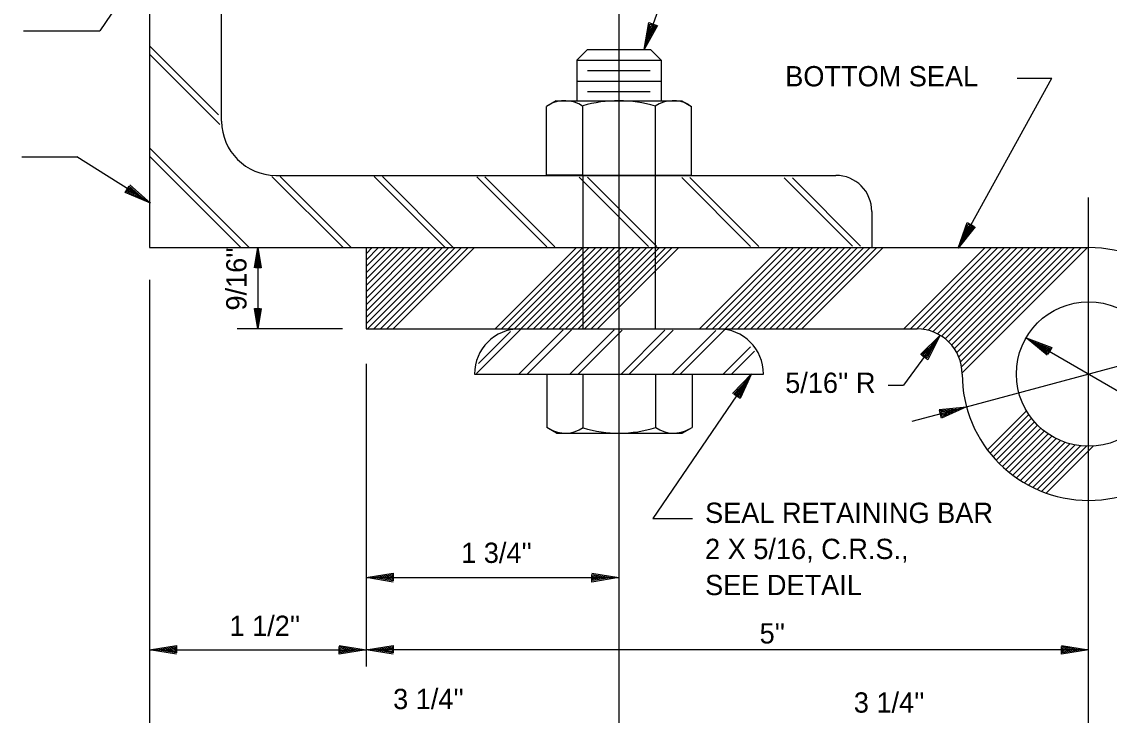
# Model space of a CAD drawing. Extents: x 22371.58 to 22374.41, y 22370.57 to 22372.4.
# Drawn here: x 22373.34 to 22373.968, y 22371.536 to 22371.936 of the extents above; entities that cross this region are included whole.
import ezdxf

# ---------------------------------------------------------------- set-up
doc = ezdxf.new("R2010")
doc.units = 0
for name, color, linetype in [('S-ANNO-DIMS', 7, 'Continuous'), ('S-ANNO-TEXT', 7, 'Continuous'), ('S-GATE-SEAL', 7, 'Continuous'), ('S-SECT-MISC', 7, 'Continuous')]:
    doc.layers.add(name, color=color, linetype=linetype)

msp = doc.modelspace()

# ---------------------------------------------------------------- linework, layer by layer
at = {"layer": 'S-ANNO-DIMS'}
for p, q in [((22373.43491, 22372.00398), (22373.38549, 22371.93085)), ((22373.6993, 22371.92005), (22373.71761, 22371.97098)), ((22373.68487, 22371.95267), (22373.68487, 22371.52103)), ((22373.34148, 22371.93085), (22373.38549, 22371.93085)), ((22373.70077, 22371.92412), (22373.70077, 22371.92412)), ((22373.6993, 22371.92005), (22373.6993, 22371.92005)), ((22373.8805, 22371.8054), (22373.9346, 22371.90356)), ((22373.91461, 22371.90356), (22373.9346, 22371.90356)), ((22373.34041, 22371.85808), (22373.37223, 22371.85808)), ((22373.41459, 22371.83149), (22373.37223, 22371.85808)), ((22373.41092, 22371.83379), (22373.41092, 22371.83379)), ((22373.41459, 22371.83149), (22373.41459, 22371.83149)), ((22373.95571, 22371.51808), (22373.95571, 22371.83464)), ((22373.47654, 22371.80582), (22373.47654, 22371.75894)), ((22373.47654, 22371.80582), (22373.47654, 22371.80582)), ((22373.8805, 22371.8054), (22373.8805, 22371.8054)), ((22373.88259, 22371.80919), (22373.88259, 22371.80919)), ((22373.47654, 22371.80257), (22373.47654, 22371.80257)), ((22373.41404, 22371.78718), (22373.41404, 22371.51808)), ((22373.47654, 22371.76219), (22373.47654, 22371.76219)), ((22373.52536, 22371.75894), (22373.46471, 22371.75894)), ((22373.47654, 22371.75894), (22373.47654, 22371.75894)), ((22373.87009, 22371.75527), (22373.84894, 22371.7264)), ((22373.87009, 22371.75527), (22373.87009, 22371.75527)), ((22373.91964, 22371.75373), (22373.99181, 22371.71206)), ((22373.91964, 22371.75373), (22373.91964, 22371.75373)), ((22373.86753, 22371.75177), (22373.86753, 22371.75177)), ((22373.88529, 22371.71402), (22374.02616, 22371.75177)), ((22373.92339, 22371.75156), (22373.92339, 22371.75156)), ((22373.53904, 22371.73875), (22373.53904, 22371.56422)), ((22373.76132, 22371.73303), (22373.70447, 22371.6496)), ((22373.75888, 22371.72944), (22373.75888, 22371.72944)), ((22373.76132, 22371.73303), (22373.76132, 22371.73303)), ((22373.84018, 22371.7264), (22373.84894, 22371.7264)), ((22373.85399, 22371.70563), (22373.8853, 22371.71402)), ((22373.88111, 22371.71289), (22373.88111, 22371.71289)), ((22373.8853, 22371.71402), (22373.8853, 22371.71402)), ((22373.70447, 22371.6496), (22373.72723, 22371.6496)), ((22373.53904, 22371.61548), (22373.68487, 22371.61548)), ((22373.53904, 22371.61548), (22373.53904, 22371.61548)), ((22373.54337, 22371.61548), (22373.54337, 22371.61548)), ((22373.68054, 22371.61548), (22373.68054, 22371.61548)), ((22373.68487, 22371.61548), (22373.68487, 22371.61548)), ((22373.41404, 22371.57381), (22373.53904, 22371.57381)), ((22373.41404, 22371.57381), (22373.41404, 22371.57381)), ((22373.41837, 22371.57381), (22373.41837, 22371.57381)), ((22373.53471, 22371.57381), (22373.53471, 22371.57381)), ((22373.95571, 22371.57381), (22373.53904, 22371.57381)), ((22373.53904, 22371.57381), (22373.53904, 22371.57381)), ((22373.54337, 22371.57381), (22373.54337, 22371.57381)), ((22373.95137, 22371.57381), (22373.95137, 22371.57381)), ((22373.95571, 22371.57381), (22373.95571, 22371.57381))]:
    msp.add_line(p, q, dxfattribs=at)
for points in [[(22373.70701, 22371.93384), (22373.6993, 22371.92005), (22373.70214, 22371.93559), (22373.7063, 22371.93409), (22373.70077, 22371.92412), (22373.70269, 22371.93467), (22373.70536, 22371.93372), (22373.70217, 22371.92805), (22373.70326, 22371.93377), (22373.70435, 22371.93337), (22373.70364, 22371.93212)], [(22373.40277, 22371.84196), (22373.41459, 22371.83149), (22373.40002, 22371.83758), (22373.40237, 22371.84132), (22373.41092, 22371.83379), (22373.40103, 22371.83793), (22373.40253, 22371.84033), (22373.40739, 22371.83601), (22373.40204, 22371.83829), (22373.40265, 22371.83928), (22373.40373, 22371.83831)], [(22373.89028, 22371.8178), (22373.8805, 22371.8054), (22373.88576, 22371.8203), (22373.88962, 22371.81816), (22373.88259, 22371.80919), (22373.88616, 22371.81931), (22373.88864, 22371.81794), (22373.8846, 22371.81285), (22373.88657, 22371.81833), (22373.88759, 22371.81776), (22373.88669, 22371.81664)], [(22373.4746, 22371.79413), (22373.47654, 22371.80582), (22373.47848, 22371.79413), (22373.47516, 22371.79413), (22373.47654, 22371.80257), (22373.47785, 22371.79463), (22373.47573, 22371.79463), (22373.47654, 22371.79944), (22373.47723, 22371.79513), (22373.47635, 22371.79513), (22373.47654, 22371.79619)], [(22373.47848, 22371.77063), (22373.47654, 22371.75894), (22373.4746, 22371.77063), (22373.47791, 22371.77063), (22373.47654, 22371.76219), (22373.47523, 22371.77013), (22373.47735, 22371.77013), (22373.47654, 22371.76532), (22373.47585, 22371.76963), (22373.47673, 22371.76963), (22373.47654, 22371.76857)], [(22373.8588, 22371.74423), (22373.87009, 22371.75527), (22373.86297, 22371.74117), (22373.8594, 22371.74378), (22373.86753, 22371.75177), (22373.86268, 22371.74221), (22373.8604, 22371.74387), (22373.86507, 22371.74841), (22373.86241, 22371.74323), (22373.86147, 22371.74392), (22373.86251, 22371.74491)], [(22373.93185, 22371.74369), (22373.91964, 22371.75373), (22373.93443, 22371.74817), (22373.93223, 22371.74435), (22373.92339, 22371.75156), (22373.93343, 22371.74778), (22373.93202, 22371.74533), (22373.92701, 22371.74948), (22373.93244, 22371.74739), (22373.93186, 22371.74638), (22373.93076, 22371.74731)], [(22373.75041, 22371.7216), (22373.76132, 22371.73303), (22373.75467, 22371.71869), (22373.75103, 22371.72118), (22373.75888, 22371.72944), (22373.75436, 22371.71972), (22373.75203, 22371.72131), (22373.75653, 22371.72601), (22373.75405, 22371.72074), (22373.75309, 22371.72139), (22373.75409, 22371.72242)], [(22373.86958, 22371.71249), (22373.8853, 22371.71402), (22373.87091, 22371.70749), (22373.86977, 22371.71176), (22373.88111, 22371.71289), (22373.87134, 22371.70847), (22373.87061, 22371.71121), (22373.87709, 22371.71182), (22373.87177, 22371.70944), (22373.87147, 22371.71057), (22373.8729, 22371.71069)], [(22373.55462, 22371.61289), (22373.53904, 22371.61548), (22373.55462, 22371.61806), (22373.55462, 22371.61364), (22373.54337, 22371.61548), (22373.55396, 22371.61723), (22373.55396, 22371.61439), (22373.54754, 22371.61548), (22373.55329, 22371.61639), (22373.55329, 22371.61523), (22373.55187, 22371.61548)], [(22373.66929, 22371.61806), (22373.68487, 22371.61548), (22373.66929, 22371.61289), (22373.66929, 22371.61731), (22373.68054, 22371.61548), (22373.66996, 22371.61373), (22373.66996, 22371.61656), (22373.67637, 22371.61548), (22373.67062, 22371.61456), (22373.67062, 22371.61573), (22373.67204, 22371.61548)], [(22373.42962, 22371.57123), (22373.41404, 22371.57381), (22373.42962, 22371.57639), (22373.42962, 22371.57198), (22373.41837, 22371.57381), (22373.42896, 22371.57556), (22373.42896, 22371.57273), (22373.42254, 22371.57381), (22373.42829, 22371.57473), (22373.42829, 22371.57356), (22373.42687, 22371.57381)], [(22373.52346, 22371.57639), (22373.53904, 22371.57381), (22373.52346, 22371.57123), (22373.52346, 22371.57564), (22373.53471, 22371.57381), (22373.52412, 22371.57206), (22373.52412, 22371.57489), (22373.53054, 22371.57381), (22373.52479, 22371.57289), (22373.52479, 22371.57406), (22373.52621, 22371.57381)], [(22373.55462, 22371.57123), (22373.53904, 22371.57381), (22373.55462, 22371.57639), (22373.55462, 22371.57198), (22373.54337, 22371.57381), (22373.55396, 22371.57556), (22373.55396, 22371.57273), (22373.54754, 22371.57381), (22373.55329, 22371.57473), (22373.55329, 22371.57356), (22373.55187, 22371.57381)], [(22373.94012, 22371.57639), (22373.95571, 22371.57381), (22373.94012, 22371.57123), (22373.94012, 22371.57564), (22373.95137, 22371.57381), (22373.94079, 22371.57206), (22373.94079, 22371.57489), (22373.94721, 22371.57381), (22373.94146, 22371.57289), (22373.94146, 22371.57406), (22373.94287, 22371.57381)]]:
    msp.add_lwpolyline(points, dxfattribs=at)
at = {"layer": 'S-GATE-SEAL'}
for p, q in [((22373.45571, 22371.87874), (22373.45571, 22372.31624)), ((22373.41404, 22372.22249), (22373.41404, 22371.80582)), ((22373.48696, 22371.84749), (22373.80987, 22371.84749)), ((22373.83071, 22371.82665), (22373.83071, 22371.80582)), ((22373.41404, 22371.80582), (22373.83071, 22371.80582)), ((22373.53904, 22371.80582), (22373.53904, 22371.75894)), ((22373.53904, 22371.80582), (22373.95571, 22371.80582)), ((22373.57938, 22371.80582), (22373.53904, 22371.76548)), ((22373.57203, 22371.80582), (22373.53904, 22371.77283)), ((22373.56465, 22371.80582), (22373.53904, 22371.78021)), ((22373.5573, 22371.80582), (22373.53904, 22371.78756)), ((22373.54992, 22371.80582), (22373.53904, 22371.79493)), ((22373.54624, 22371.80582), (22373.53904, 22371.79862)), ((22373.55361, 22371.80582), (22373.53904, 22371.79125)), ((22373.54255, 22371.80582), (22373.53904, 22371.80231)), ((22373.56099, 22371.80582), (22373.53904, 22371.78387)), ((22373.56834, 22371.80582), (22373.53904, 22371.77652)), ((22373.57572, 22371.80582), (22373.53904, 22371.76914)), ((22373.58307, 22371.80582), (22373.53904, 22371.76179)), ((22373.58676, 22371.80582), (22373.53988, 22371.75894)), ((22373.59044, 22371.80582), (22373.54357, 22371.75894)), ((22373.59411, 22371.80582), (22373.54724, 22371.75894)), ((22373.5978, 22371.80582), (22373.55092, 22371.75894)), ((22373.60149, 22371.80582), (22373.55461, 22371.75894)), ((22373.6604, 22371.80582), (22373.61353, 22371.75894)), ((22373.66407, 22371.80582), (22373.61719, 22371.75894)), ((22373.66776, 22371.80582), (22373.62088, 22371.75894)), ((22373.67144, 22371.80582), (22373.62457, 22371.75894)), ((22373.67513, 22371.80582), (22373.62826, 22371.75894)), ((22373.6788, 22371.80582), (22373.63192, 22371.75894)), ((22373.68249, 22371.80582), (22373.63561, 22371.75894)), ((22373.68617, 22371.80582), (22373.6393, 22371.75894)), ((22373.68986, 22371.80582), (22373.64299, 22371.75894)), ((22373.69353, 22371.80582), (22373.64665, 22371.75894)), ((22373.69722, 22371.80582), (22373.65034, 22371.75894)), ((22373.7009, 22371.80582), (22373.65403, 22371.75894)), ((22373.70459, 22371.80582), (22373.65772, 22371.75894)), ((22373.70826, 22371.80582), (22373.66138, 22371.75894)), ((22373.71194, 22371.80582), (22373.66507, 22371.75894)), ((22373.71563, 22371.80582), (22373.66876, 22371.75894)), ((22373.71932, 22371.80582), (22373.67244, 22371.75894)), ((22373.77826, 22371.80582), (22373.73138, 22371.75894)), ((22373.78192, 22371.80582), (22373.73505, 22371.75894)), ((22373.78561, 22371.80582), (22373.73874, 22371.75894)), ((22373.7893, 22371.80582), (22373.74242, 22371.75894)), ((22373.79299, 22371.80582), (22373.74611, 22371.75894)), ((22373.79665, 22371.80582), (22373.74978, 22371.75894)), ((22373.80034, 22371.80582), (22373.75347, 22371.75894)), ((22373.80403, 22371.80582), (22373.75715, 22371.75894)), ((22373.80772, 22371.80582), (22373.76084, 22371.75894)), ((22373.81138, 22371.80582), (22373.76451, 22371.75894)), ((22373.81507, 22371.80582), (22373.76819, 22371.75894)), ((22373.81876, 22371.80582), (22373.77188, 22371.75894)), ((22373.82244, 22371.80582), (22373.77557, 22371.75894)), ((22373.82611, 22371.80582), (22373.77924, 22371.75894)), ((22373.82242, 22371.80582), (22373.77924, 22371.76263)), ((22373.8298, 22371.80582), (22373.78292, 22371.75894)), ((22373.83349, 22371.80582), (22373.78661, 22371.75894)), ((22373.83717, 22371.80582), (22373.7903, 22371.75894)), ((22373.89611, 22371.80582), (22373.84924, 22371.75894)), ((22373.8998, 22371.80582), (22373.85292, 22371.75894)), ((22373.90346, 22371.80581), (22373.85658, 22371.75893)), ((22373.90715, 22371.80582), (22373.86006, 22371.75873)), ((22373.91083, 22371.80581), (22373.86316, 22371.75814)), ((22373.91453, 22371.80582), (22373.86597, 22371.75726)), ((22373.91818, 22371.80581), (22373.86851, 22371.75613)), ((22373.92188, 22371.80582), (22373.87086, 22371.7548)), ((22373.92556, 22371.80581), (22373.87301, 22371.75326)), ((22373.92926, 22371.80582), (22373.87485, 22371.75141)), ((22373.93291, 22371.80581), (22373.87673, 22371.74962)), ((22373.93661, 22371.80582), (22373.87857, 22371.74778)), ((22373.94029, 22371.80581), (22373.87971, 22371.74523)), ((22373.94399, 22371.80582), (22373.88088, 22371.74272)), ((22373.94764, 22371.80581), (22373.88182, 22371.73999)), ((22373.95134, 22371.80582), (22373.88249, 22371.73697)), ((22373.95502, 22371.80581), (22373.88281, 22371.7336)), ((22373.53904, 22371.75894), (22373.85675, 22371.75894)), ((22373.62758, 22371.75894), (22373.74216, 22371.75894)), ((22373.60154, 22371.7329), (22373.76821, 22371.7329)), ((22373.91984, 22371.71172), (22373.89734, 22371.68922)), ((22373.92127, 22371.70946), (22373.89918, 22371.68737)), ((22373.92282, 22371.70734), (22373.90062, 22371.68514)), ((22373.92449, 22371.70532), (22373.90247, 22371.6833)), ((22373.92628, 22371.70342), (22373.90417, 22371.68132)), ((22373.92812, 22371.70158), (22373.90602, 22371.67948)), ((22373.93018, 22371.69998), (22373.90799, 22371.67778)), ((22373.93232, 22371.69842), (22373.91, 22371.6761)), ((22373.93458, 22371.697), (22373.91207, 22371.67449)), ((22373.93697, 22371.69569), (22373.91422, 22371.67294)), ((22373.93947, 22371.69453), (22373.91641, 22371.67148)), ((22373.94213, 22371.69351), (22373.91871, 22371.67008)), ((22373.94496, 22371.69264), (22373.92106, 22371.66875)), ((22373.94796, 22371.69196), (22373.92349, 22371.66749)), ((22373.95114, 22371.69148), (22373.92599, 22371.66632)), ((22373.95459, 22371.69124), (22373.92857, 22371.66522)), ((22373.95835, 22371.69131), (22373.93125, 22371.66421))]:
    msp.add_line(p, q, dxfattribs=at)
for points in [[(22373.45388, 22371.88239), (22373.41432, 22371.92196)], [(22373.45469, 22371.87687), (22373.41434, 22371.91723)], [(22373.4715, 22371.80586), (22373.41447, 22371.86289)], [(22373.46679, 22371.80585), (22373.41447, 22371.85816)], [(22373.52558, 22371.80599), (22373.48463, 22371.84692)], [(22373.53028, 22371.806), (22373.48936, 22371.84691)], [(22373.58437, 22371.80612), (22373.54373, 22371.84676)], [(22373.58907, 22371.80613), (22373.54846, 22371.84675)], [(22373.64316, 22371.80626), (22373.60283, 22371.84659)], [(22373.64786, 22371.80627), (22373.60756, 22371.84657)], [(22373.70194, 22371.80639), (22373.66192, 22371.84641)], [(22373.70665, 22371.8064), (22373.66665, 22371.84639)], [(22373.76074, 22371.80653), (22373.72103, 22371.84625)], [(22373.76544, 22371.80654), (22373.72575, 22371.84623)], [(22373.81953, 22371.80666), (22373.78012, 22371.84607)], [(22373.82424, 22371.80667), (22373.78485, 22371.84606)], [(22373.60271, 22371.73314), (22373.62809, 22371.75853)], [(22373.60376, 22371.73891), (22373.62229, 22371.75744)], [(22373.62738, 22371.73307), (22373.65274, 22371.75842)], [(22373.63209, 22371.73307), (22373.65743, 22371.75841)], [(22373.65676, 22371.73299), (22373.68207, 22371.7583)], [(22373.66146, 22371.73298), (22373.68676, 22371.75828)], [(22373.68613, 22371.7329), (22373.7114, 22371.75817)], [(22373.69083, 22371.73289), (22373.7161, 22371.75816)], [(22373.7155, 22371.73281), (22373.74075, 22371.75806)], [(22373.72021, 22371.73279), (22373.74594, 22371.75854)], [(22373.74487, 22371.73272), (22373.76076, 22371.7486)], [(22373.74958, 22371.73271), (22373.76298, 22371.7461)]]:
    msp.add_lwpolyline(points, dxfattribs=at)
msp.add_circle((22373.95573, 22371.73289), 0.04167, dxfattribs=at)
for centre, radius, start, end in [((22373.48696, 22371.87874), 0.03125, 180, 270), ((22373.80987, 22371.82665), 0.02083, 0, 90), ((22373.95573, 22371.73289), 0.07292, 180, 90), ((22373.62758, 22371.7329), 0.02604, 90, 180), ((22373.74216, 22371.7329), 0.02604, 0, 90), ((22373.85677, 22371.73289), 0.02604, 0, 90)]:
    msp.add_arc(centre, radius, start, end, dxfattribs=at)
at = {"layer": 'S-SECT-MISC'}
for p, q in [((22373.66061, 22371.91399), (22373.66667, 22371.92005)), ((22373.66667, 22371.92005), (22373.70305, 22371.92005)), ((22373.70911, 22371.91399), (22373.70305, 22371.92005)), ((22373.66061, 22371.91399), (22373.70911, 22371.91399)), ((22373.66061, 22371.91399), (22373.66061, 22371.89055)), ((22373.70911, 22371.91399), (22373.70911, 22371.89055)), ((22373.66674, 22371.90792), (22373.7028, 22371.90792)), ((22373.66061, 22371.90186), (22373.70911, 22371.90186)), ((22373.66674, 22371.89582), (22373.7028, 22371.89582)), ((22373.64859, 22371.89055), (22373.64299, 22371.8873)), ((22373.64299, 22371.84755), (22373.64299, 22371.8873)), ((22373.64859, 22371.89055), (22373.72111, 22371.89055)), ((22373.66388, 22371.88738), (22373.66388, 22371.84755)), ((22373.70582, 22371.88738), (22373.70582, 22371.84755)), ((22373.72111, 22371.89055), (22373.72672, 22371.8873)), ((22373.72672, 22371.84755), (22373.72672, 22371.8873)), ((22373.64299, 22371.84755), (22373.72672, 22371.84755)), ((22373.66417, 22371.84755), (22373.64299, 22371.84755)), ((22373.66404, 22371.84749), (22373.66404, 22371.75894)), ((22373.70571, 22371.84749), (22373.70571, 22371.75894)), ((22373.60154, 22371.7329), (22373.60154, 22371.7329)), ((22373.64324, 22371.73275), (22373.72699, 22371.73275)), ((22373.64324, 22371.73275), (22373.64324, 22371.70206)), ((22373.66413, 22371.70198), (22373.66413, 22371.73275)), ((22373.70609, 22371.70198), (22373.70609, 22371.73275)), ((22373.72699, 22371.73275), (22373.72699, 22371.70206)), ((22373.76821, 22371.7329), (22373.76821, 22371.7329)), ((22373.64886, 22371.69881), (22373.64324, 22371.70206)), ((22373.64886, 22371.69881), (22373.72136, 22371.69881)), ((22373.72136, 22371.69881), (22373.72699, 22371.70206))]:
    msp.add_line(p, q, dxfattribs=at)
for centre, radius, start, end in [((22373.65358, 22371.8724), 0.01818, 55.48902, 120.28759), ((22373.68459, 22371.81782), 0.07273, 73.01837, 106.49659), ((22373.71613, 22371.8724), 0.01818, 59.71241, 124.51098), ((22373.65384, 22371.71696), 0.01818, 239.71241, 304.51098), ((22373.68484, 22371.77154), 0.07273, 253.50341, 286.98163), ((22373.71639, 22371.71696), 0.01818, 235.48902, 300.28759)]:
    msp.add_arc(centre, radius, start, end, dxfattribs=at)

# ---------------------------------------------------------------- texts
at = {"layer": 'S-ANNO-DIMS'}
msp.add_text("9/16''", height=0.011698, rotation=90, dxfattribs=at).set_placement((22373.47004, 22371.76952))
for s, height, p in [("5/16'' R", 0.011698, (22373.78075, 22371.722)), ('SEAL RETAINING BAR', 0.0116979, (22373.73452, 22371.64699)), ("1 3/4''", 0.011698, (22373.59386, 22371.62393)), ('2 X 5/16, C.R.S.,', 0.0116979, (22373.73452, 22371.62617)), ('SEE DETAIL', 0.011698, (22373.73452, 22371.60536)), ("1 1/2''", 0.011698, (22373.46024, 22371.58182)), ("5''", 0.011698, (22373.76598, 22371.57746)), ("3 1/4''", 0.011698, (22373.5546, 22371.53961)), ("3 1/4''", 0.011698, (22373.82031, 22371.53757))]:
    msp.add_text(s, height=height, dxfattribs=at).set_placement(p)
at = {"layer": 'S-ANNO-TEXT'}
msp.add_text('BOTTOM SEAL', height=0.0116979, dxfattribs=at).set_placement((22373.78076, 22371.89883))

doc.saveas('drawing.dxf')
